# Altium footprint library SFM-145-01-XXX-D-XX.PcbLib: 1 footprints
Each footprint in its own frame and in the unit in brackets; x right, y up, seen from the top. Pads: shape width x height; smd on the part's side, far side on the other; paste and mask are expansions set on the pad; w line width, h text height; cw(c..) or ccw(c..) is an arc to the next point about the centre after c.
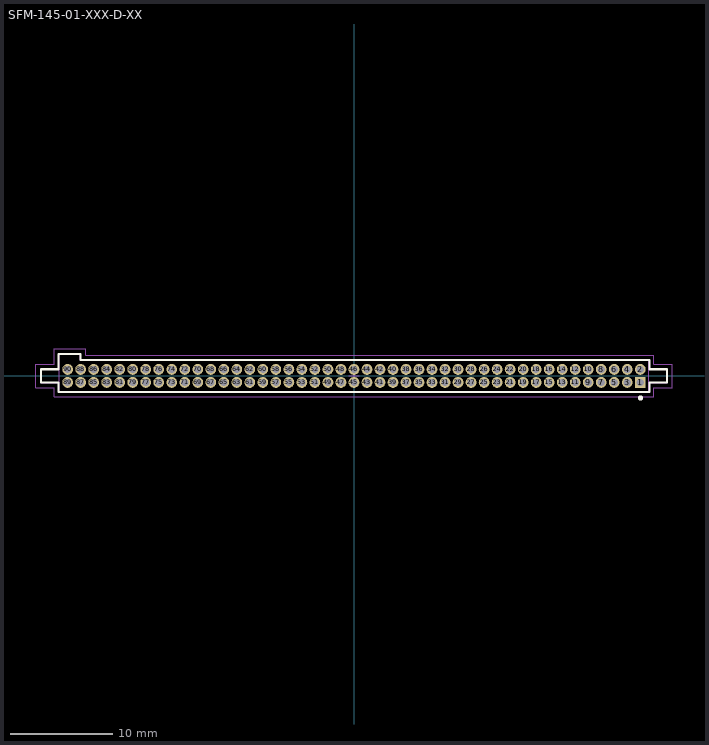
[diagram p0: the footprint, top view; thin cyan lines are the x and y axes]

## SFM-145-01-XXX-D-XX [mm] "1.27mm pitch, socket strip; assembly, double row"
height 4.57
pads (90):
  rect 1.05x1.05 / inner round 1.05 / far side rect 1.05x1.05 hole 0.7 mask+0: 1(27.935,-0.635)
  round 1.05 hole 0.7 mask+0: 2(27.935,0.635) 3(26.665,-0.635) 4(26.665,0.635) 5(25.395,-0.635) 6(25.395,0.635) 7(24.125,-0.635) 8(24.125,0.635) 9(22.855,-0.635) 10(22.855,0.635) 11(21.585,-0.635) 12(21.585,0.635) 13(20.315,-0.635) 14(20.315,0.635) 15(19.045,-0.635) 16(19.045,0.635) 17(17.775,-0.635) 18(17.775,0.635) 19(16.505,-0.635) 20(16.505,0.635) 21(15.235,-0.635) 22(15.235,0.635) 23(13.965,-0.635) 24(13.965,0.635) 25(12.695,-0.635) 26(12.695,0.635) 27(11.425,-0.635) 28(11.425,0.635) 29(10.155,-0.635) 30(10.155,0.635) 31(8.885,-0.635) 32(8.885,0.635) 33(7.615,-0.635) 34(7.615,0.635) 35(6.345,-0.635) 36(6.345,0.635) 37(5.075,-0.635) 38(5.075,0.635) 39(3.805,-0.635) 40(3.805,0.635) 41(2.535,-0.635) 42(2.535,0.635) 43(1.265,-0.635) 44(1.265,0.635) 45(-0.005,-0.635) 46(-0.005,0.635) 47(-1.275,-0.635) 48(-1.275,0.635) 49(-2.545,-0.635) 50(-2.545,0.635) 51(-3.815,-0.635) 52(-3.815,0.635) 53(-5.085,-0.635) 54(-5.085,0.635) 55(-6.355,-0.635) 56(-6.355,0.635) 57(-7.625,-0.635) 58(-7.625,0.635) 59(-8.895,-0.635) 60(-8.895,0.635) 61(-10.165,-0.635) 62(-10.165,0.635) 63(-11.435,-0.635) 64(-11.435,0.635) 65(-12.705,-0.635) 66(-12.705,0.635) 67(-13.975,-0.635) 68(-13.975,0.635) 69(-15.245,-0.635) 70(-15.245,0.635) 71(-16.515,-0.635) 72(-16.515,0.635) 73(-17.785,-0.635) 74(-17.785,0.635) 75(-19.055,-0.635) 76(-19.055,0.635) 77(-20.325,-0.635) 78(-20.325,0.635) 79(-21.595,-0.635) 80(-21.595,0.635) 81(-22.865,-0.635) 82(-22.865,0.635) 83(-24.135,-0.635) 84(-24.135,0.635) 85(-25.405,-0.635) 86(-25.405,0.635) 87(-26.675,-0.635) 88(-26.675,0.635) 89(-27.945,-0.635) 90(-27.945,0.635)
Top Overlay:
  circle w0.25: c27.95,-2.15 r0.125
  lines w0.2: -30.55,-0.65 -28.85,-0.65 -28.85,-1.55 28.85,-1.55 28.85,-0.65 30.55,-0.65 30.55,0.65 28.85,0.65 28.85,1.55 -26.7,1.55 -26.7,2.15 -28.85,2.15 -28.85,0.65 -30.55,0.65 -30.55,-0.65
Mechanical 12:
  lines w0.001: -30.55,-0.65 -28.75,-0.65 -28.75,-1.55 28.75,-1.55 28.75,-0.65 30.55,-0.65 30.55,0.65 28.75,0.65 28.75,1.55 -26.7,1.55 -26.7,2.15 -28.75,2.15 -28.75,0.65 -30.55,0.65 -30.55,-0.65
Mechanical 13:
  lines w0.1: -28.75,-0.65 -28.75,-1.55 28.75,-1.55 28.75,-0.65 ; -28.75,-0.65 -30.55,-0.65 -30.55,0.65 -28.75,0.65 ; -28.75,-0.65 -28.75,0.65 ; -28.75,0.65 -28.75,2.15 -26.7,2.15 -26.7,1.55 28.75,1.55 28.75,0.65 ; 28.75,-0.65 30.55,-0.65 30.55,0.65 28.75,0.65 ; 28.75,-0.65 28.75,0.65
  text ".Designator" at 0,-0.127 h1.52
Mechanical 15:
  lines w0.05: -0.5,0 0.5,0 ; 0,-0.5 0,0.5 ; -31.05,-1.15 -29.25,-1.15 -29.25,-2.032 29.25,-2.032 29.25,-1.15 31.05,-1.15 31.05,1.15 29.25,1.15 29.25,2.032 -26.2,2.032 -26.2,2.65 -29.25,2.65 -29.25,1.15 -31.05,1.15 -31.05,-1.15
